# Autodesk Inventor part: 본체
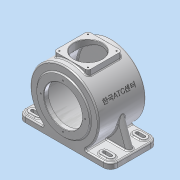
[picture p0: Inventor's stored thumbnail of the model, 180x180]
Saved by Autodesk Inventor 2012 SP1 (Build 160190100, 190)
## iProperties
Created: 2015-06
Part Number: 본체
Material: 알루미늄-6061
Document SubType Name: Modeling
Designer: Administrator
Density: 2.71 g/cm^3
Mass: 3275.25 g
Surface Area: 2299.72 cm^2
Volume: 1208.58 cm^3
Author: Administrator
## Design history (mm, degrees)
sketch "스케치1"
  geometry: L1 (115, -59)-(-115, -59); L2 (-115, -59)-(-115, 59); L3 (-115, 59)-(115, 59); L4 (115, 59)-(115, -59); L5 (115, -59)-(-115, 59); 2 further points
  constraints: 10 end point, 2 parallel, 1 coincident, 1 horizontal, 1 midpoint, 1 perpendicular
  dimensions: "d0" = 230 distance of L2.end L3.end; "d1" = 118 distance of L1.end L2.end
extrude "돌출1" new body sketch "스케치1" distance "d2" = 14; taper "d3" = 0 deg
sketch "스케치2"
  geometry: L1 (-115, 0)-(115, 0) reference; L2 (115, -14)-(-115, -14) reference; C1 r 85 at (0, 71); 2 further points
  constraints: 1 centre point, 1 midpoint, 1 vertical alignment
  dimensions: "d4" = 170 diameter of C1; "d5" = 85 distance from line of C1.centre L2
extrude "돌출2" join sketch "스케치2" stored distance "d6" = 118; taper "d7" = 0 deg
sketch "스케치3"
  geometry: C1 r 65 at (115, -85); A1 r 85 centre (115, -85) between (68.267, -14) and (161.733, -14) reference; 1 further point
  constraints: 1 centre point, 1 coincident
  dimensions: "d8" = 130 diameter of C1
extrude "돌출3" join sketch "스케치3" distance "d9" = 13; taper "d10" = 0 deg
sketch "스케치4"
  geometry: C1 r 77 at (0, 71); A1 r 85 centre (0, 71) between (46.733, 0) and (-46.733, 0) reference; 1 further point
  constraints: 1 centre point, 1 coincident
  dimensions: "d11" = 154 diameter of C1
extrude "돌출4" cut sketch "스케치4" stored distance "d12" = 102; taper "d13" = 0 deg
sketch "스케치5"
  geometry: C1 r 65 at (115, 85); A1 r 85 centre (115, 85) between (161.733, 14) and (68.267, 14) reference; 1 further point
  constraints: 1 centre point, 1 coincident
  dimensions: "d14" = 130 diameter of C1
extrude "돌출5" join sketch "스케치5" distance "d15" = 3; taper "d16" = 0 deg
hole "구멍1" diameter "d19" = 95; stored, may be unused: countersink angle "d23" = 90 deg, drill point angle "d25" = 0 deg; dims "d17" = 10, "d18" = 10, "d20" = 6, "d21" = 4, "d22" = 2, "d24" = 11
sketch "스케치6" dims "d26" = 110
  geometry: C1 r 47.5 at (0, 0) reference; 3 further points
  constraints: 2 vertical alignment, 1 coincident, 2 other
hole "구멍2" sketch "스케치6" at (0, 55) diameter "d27" = 3.242; stored, may be unused: countersink angle "d31" = 90 deg, drill point angle "d33" = 118 deg; dims "d28" = 20, "d29" = 4, "d30" = 2, "d32" = 30
sketch "스케치7"
  geometry: C1 r 31 at (0, 0); A1 r 85 centre (0, 0) between (46.733, -71) and (-46.733, -71) reference; 1 further point
  constraints: 1 centre point, 1 coincident
  dimensions: "d37" = 62 diameter of C1
extrude "돌출6" join sketch "스케치7" distance "d38" = 3.5; taper "d39" = -25 deg
hole "구멍3" diameter "d42" = 30; stored, may be unused: countersink angle "d46" = 90 deg, drill point angle "d48" = 0 deg; dims "d40" = 10, "d41" = 10, "d43" = 30, "d44" = 47, "d45" = 14, "d47" = 17
node "작업 평면1"
sketch "스케치8"
  geometry: L1 (35.5, -42.5)-(-35.5, -42.5); L2 (-42.5, -35.5)-(-42.5, 35.5); L3 (-35.5, 42.5)-(35.5, 42.5); L4 (42.5, 35.5)-(42.5, -35.5); L5 (42.5, -42.5)-(-42.5, 42.5); A1 r 7 centre (35.5, 35.5) between (42.5, 35.5) and (35.5, 42.5); A2 r 7 centre (35.5, -35.5) between (35.5, -42.5) and (42.5, -35.5); A3 r 7 centre (-35.5, 35.5) between (-35.5, 42.5) and (-42.5, 35.5); A4 r 7 centre (-35.5, -35.5) between (-42.5, -35.5) and (-35.5, -42.5); 4 further points
  constraints: 10 end point, 8 point on circle, 8 point on line, 8 tangent, 4 centre point, 3 equal radius, 2 parallel, 1 coincident, 1 horizontal, 1 midpoint, 1 perpendicular
  dimensions: "d50" = 85 distance of L5.end point (42.5, 42.5); "d51" = 85 distance of point (-42.5, -42.5) L5.end; "d52" = 7 radius of A1
extrude "돌출7" join sketch "스케치8" stored distance "d53" = 3.5; taper "d54" = 0 deg
sketch "스케치9"
  geometry: L1 (-35.5, -35.5)-(35.5, -35.5); L2 (35.5, -35.5)-(35.5, 35.5); L3 (35.5, 35.5)-(-35.5, 35.5); L4 (-35.5, 35.5)-(-35.5, -35.5); L5 (-35.5, -35.5)-(35.5, 35.5); 6 further points
  constraints: 10 end point, 5 coincident, 2 parallel, 1 horizontal, 1 midpoint, 1 perpendicular
  dimensions: "d55" = 71 distance of L3.end L2.end; "d56" = 71 distance of L2.end L1.end
hole "구멍4" sketch "스케치9" at (-35.5, 35.5), (35.5, 35.5), (35.5, -35.5), (-35.5, -35.5) diameter "d57" = 3.242; stored, may be unused: countersink angle "d61" = 90 deg, drill point angle "d63" = 118 deg; dims "d58" = 10, "d59" = 47, "d60" = 14, "d62" = 13
sketch "스케치10"
  geometry: C1 r 35 at (0, 0); 1 further point
  constraints: 1 centre point, 1 coincident
  dimensions: "d64" = 70 diameter of C1
extrude "돌출8" cut sketch "스케치10" stored distance "d65" = 3.5; taper "d66" = 0 deg
sketch "스케치11"
  geometry: L1 (-46.733, 0)-(-115, 0) reference; L2 (-84.87, 66.297)-(-109, 0); L3 (-115, 0)-(-115, -14) reference; A1 r 85 centre (0, 71) between (46.733, 0) and (-46.733, 0) reference; 1 further point
  constraints: 2 end point, 1 point on circle, 1 point on line
  dimensions: "d67" = 6 distance from line of L3 L2.end; "d68" = 110 deg angle of L1 L2
feature "리브1" sketch "스케치11" dims "d69" = 1, "d70" = 15, "d71" = 0, "d72" = 0, "d73" = 1, "d74" = 1
sketch "스케치12"
  geometry: L1 (115, -59)-(115, 59) reference; L2 (-115, -59)-(115, -59) reference; L3 (81, 50)-(97, 50); L4 (97, 32)-(81, 32); A1 r 9 centre (97, 41) between (97, 32) and (97, 50); A2 r 9 centre (81, 41) between (81, 50) and (81, 32); 1 further point
  constraints: 4 end point, 4 point on circle, 4 tangent, 2 centre point, 2 parallel
  dimensions: "d75" = 16 distance of L3.start L3.end; "d76" = 18 distance between parallel lines of L4 L3; "d77" = 97 horizontal distance of point (0, 0) A1.centre; "d78" = 41 vertical distance of point (0, 0) A1.centre
extrude "돌출9" join sketch "스케치12" distance "d79" = 3; taper "d80" = 0 deg
sketch "스케치13"
  geometry: L1 (81, 50)-(97, 50) reference; L2 (97, 32)-(81, 32) reference; L3 (97, 45)-(81, 45); L4 (81, 37)-(97, 37); A1 r 9 centre (81, 41) between (81, 50) and (81, 32) reference; A2 r 9 centre (97, 41) between (97, 32) and (97, 50) reference; A3 r 4 centre (81, 41) between (81, 45) and (81, 37); A4 r 4 centre (97, 41) between (97, 37) and (97, 45); 1 further point
  constraints: 4 end point, 4 point on circle, 2 centre point, 3 other
  dimensions: "d81" = 8 distance between parallel lines of L4 L3
extrude "돌출10" cut sketch "스케치13" stored distance "d82" = 3; taper "d83" = 0 deg
node "작업 평면2"
node "작업축1"
node "작업 평면6"
  node "작업 평면5"
sketch "스케치14"
  geometry: L1 (-41.479, 6.004)-(41.479, 6.004); L2 (41.479, 6.004)-(41.479, -6.004); L3 (41.479, -6.004)-(-41.479, -6.004); L4 (-41.479, -6.004)-(-41.479, 6.004); L5 (-41.479, -6.004)-(41.479, 6.004); L6 (352.967, 0)-(-131.161, 0) reference; 2 further points
  constraints: 2 end point, 1 midpoint, 1 point on line, 1 vertical alignment, 2 other
node "작업축2"
  node "작업 평면7"
feature "엠보싱1" dims "d90" = 0.5, "d91" = 0
chamfer "모따기1" distance "d92" = 1; stored, may be unused: second distance "d93" = 2, angle "d94" = 45 deg
chamfer "모따기2" distance "d95" = 1; stored, may be unused: second distance "d96" = 2, angle "d97" = 45 deg
chamfer "모따기3" distance "d98" = 1; stored, may be unused: second distance "d99" = 2, angle "d100" = 45 deg
fillet "모깎기1" dims "d101" = 0.3, "d102" = 3, "d103" = 18, "d104" = 3
fillet "모깎기2"
fillet "모깎기4"
fillet "모깎기5" dims "d105" = 3
node "솔리드1"
pattern_circular "원형 패턴1" dims angle "d35" = 360 deg
mirror "대칭1"
mirror "대칭2"
other parameters: "d49" = -173, "d84" = -85, "d87" = 115 deg, "d88" = -85, "d89" = 25 deg
